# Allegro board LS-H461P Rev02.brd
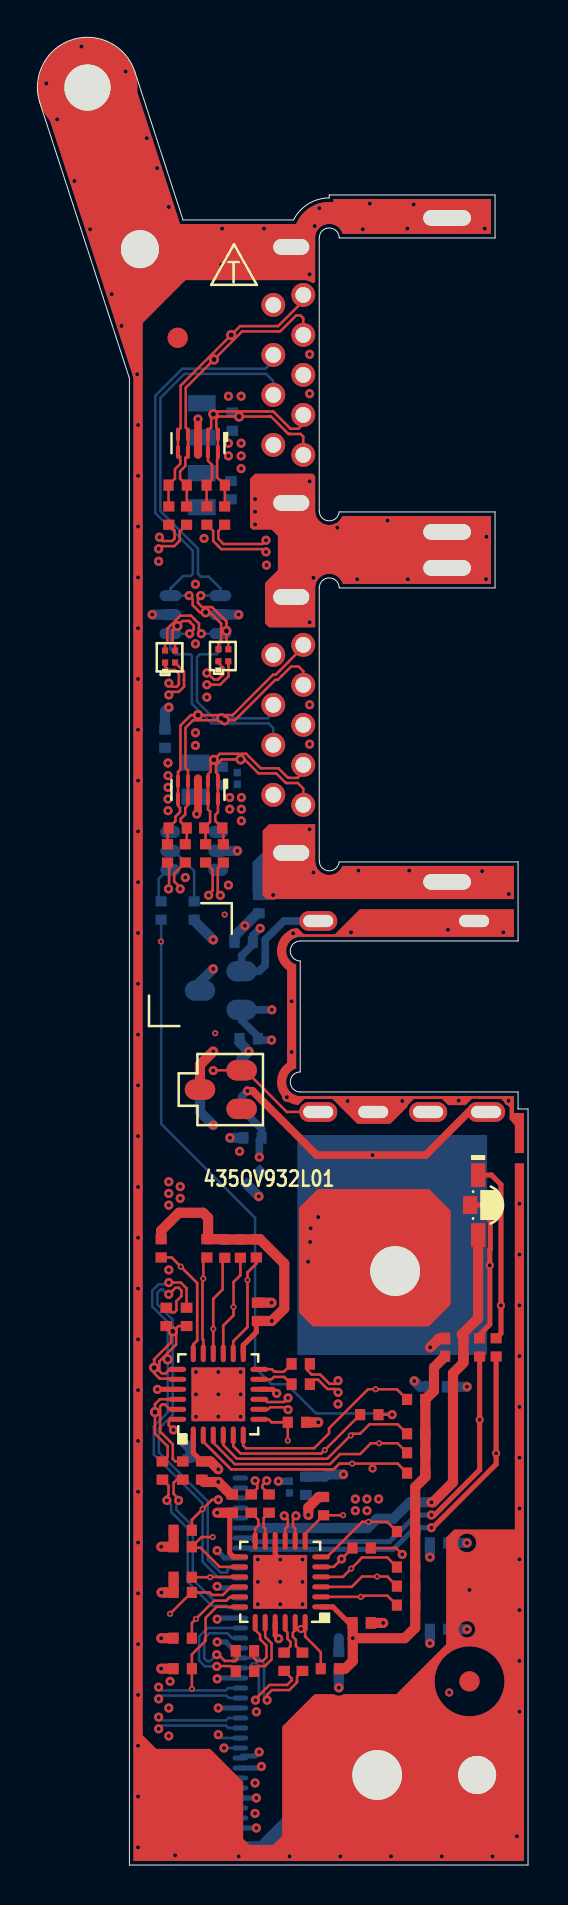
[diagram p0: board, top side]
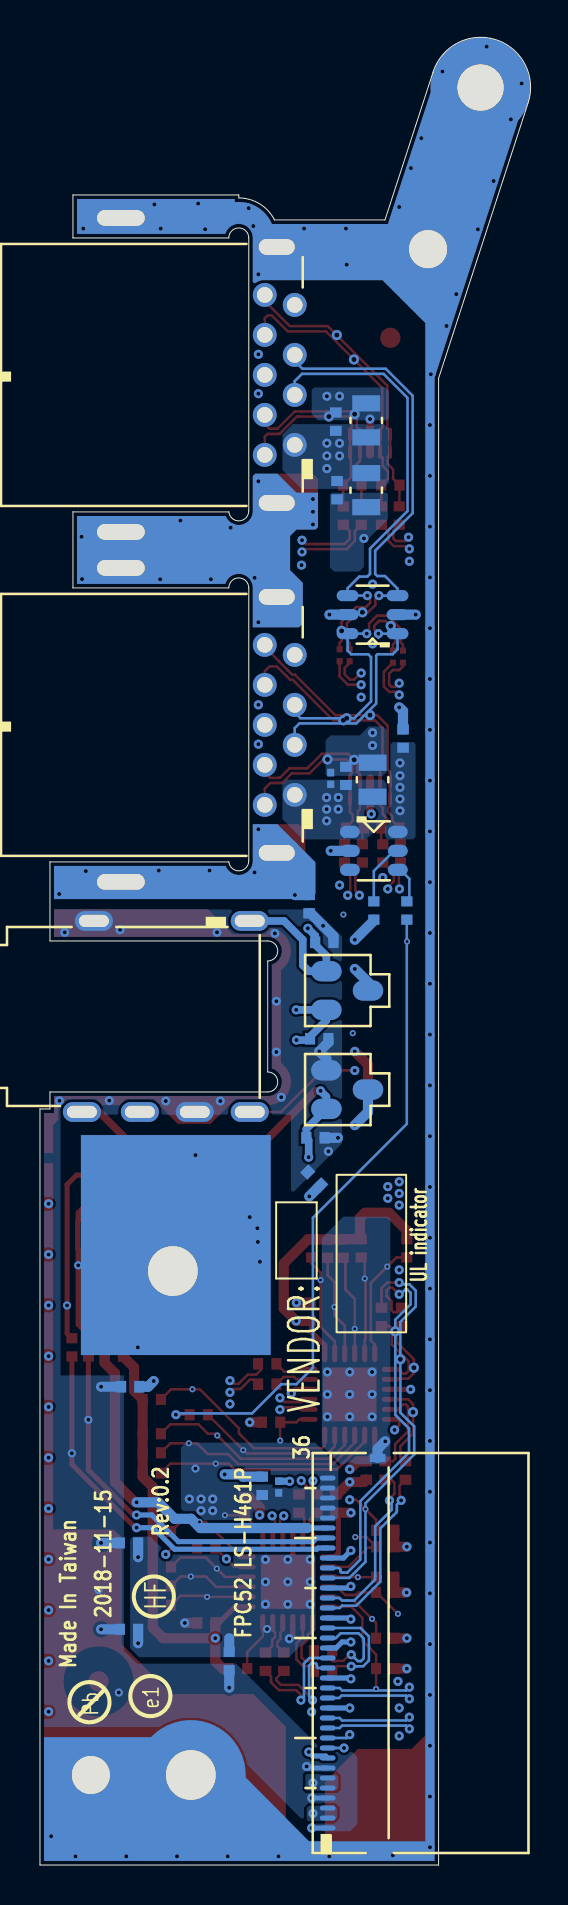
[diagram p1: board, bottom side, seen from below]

Outline 24.43 x 91.26 mm; copper layers: TOP, GND1, IN1, VCC, IN2, IN3, GND2, BOTTOM. Coordinates in mm from the lower left corner of the outline.
Outline path: 0,88.11 arc(1.6,91.26) 4.75,89.65 7.16,82.26 12.69,82.26 arc(13.43,83.06) 14.48,83.36 14.48,83.51 22.78,83.51 22.78,81.36 14.98,81.36 arc(14.48,81.86) 13.98,81.36 13.98,67.71 arc(14.45,67.21) 14.97,67.66 22.78,67.66 22.78,63.86 14.98,63.86 arc(14.48,64.36) 13.98,63.86 13.98,50.21 arc(14.45,49.71) 14.97,50.16 23.93,50.16 23.93,46.21 13.03,46.21 arc(12.53,45.71) 13.03,45.21 13.03,39.66 arc(12.53,39.16) 13.03,38.66 23.93,38.66 23.93,37.81 24.43,37.81 24.43,0 4.48,0 4.48,74.34 0,88.11

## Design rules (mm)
net group USB3: nets USB3_PRX_DTX_N2 USB3_PRX_DTX_N3 USB3_PRX_DTX_P2 USB3_PRX_DTX_P3 USB3_PTX_DRX_N2 USB3_PTX_DRX_N3 USB3_PTX_DRX_P2 USB3_PTX_DRX_P3 USB3_RX2_N_C USB3_RX2_P_C USB3_RX3_N_C USB3_RX3_P_C USB3_TX2_N_C USB3_TX2_P_C USB3_TX3_N_C USB3_TX3_P_C USB3RXDN2_C USB3RXDN3_C USB3RXDP2_C USB3RXDP3_C USB3RXN2_R USB3RXN3_R USB3RXP2_R USB3RXP3_R USB3TXDN2_C_R USB3TXDN3_C_R USB3TXDP2_C_R USB3TXDP3_C_R USB3TXN2_C USB3TXN2_RC USB3TXN3_C USB3TXN3_RC USB3TXP2_C USB3TXP2_RC USB3TXP3_C USB3TXP3_RC
net group USB 2.0: nets USB20_N2_C USB20_N3_C USB20_P2_C USB20_P3_C
nets with their own width: min track width 0.254; nets HDDHALT_LED# N98291261 N98291264 SATA_LED#
nets with their own width: min track width 0.381; nets HP_OUT_L HP_OUT_R INT_MIC
nets with their own width: min track width 0.508; nets +3VS +3VS_8713 +5VALW +USB_VCCA GND GNDA

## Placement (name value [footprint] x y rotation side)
CA33  100P_0402_50V8J  [C_0402]  11.1 36.36 180 bottom
CA48  10P_0402_50V8J  [C_0402]  10.65 46.14 180 bottom
CA49  10P_0402_50V8J  [C_0402]  10.91 41.31 180 bottom
CA50  10P_0402_50V8J  [C_0402]  10.96 47.59 90 bottom
CA51  10P_0402_50V8J  [C_0402]  11.03 34.65 225 bottom
CA52  10P_0402_50V8J  [C_0402]  20.37 23.92 180 bottom
CB1  0.01U_0402_16V7K  [C_0402]  10.89 27.2 90 top
CB2  0.1U_0402_16V7K  [C_0402]  8.1 20.18 270 top
CB3  .1U_0402_16V7K  [C_0402]  7.34 27.86 270 top
CB4  0.1U_0402_10V7K  [C_0402]  12.59 25.06 0 top
CB5  .1U_0402_16V7K  [C_0402]  6.32 27.86 270 top
CB6  0.1U_0402_10V7K  [C_0402]  12.59 24.04 0 top
CB7  .1U_0402_16V7K  [C_0402]  6.13 19.27 90 top
CB8  .1U_0402_16V7K  [C_0402]  7.15 19.27 90 top
CB9  0.01U_0402_16V7K  [C_0402]  15.64 12.1 0 top
CB10  0.1U_0402_16V7K  [C_0402]  9.62 17.62 90 top
CB11  .1U_0402_16V7K  [C_0402]  9.8 10.71 0 top
CB12  0.1U_0402_10V7K  [C_0402]  10.58 17.62 90 top
CB13  .1U_0402_16V7K  [C_0402]  9.8 9.69 0 top
CB14  0.1U_0402_10V7K  [C_0402]  11.46 17.62 90 top
CB15  .1U_0402_16V7K  [C_0402]  12.22 9.71 90 top
CB16  .1U_0402_16V7K  [C_0402]  13.14 9.71 90 top
CB17  10P_0402_50V8J  [C_0402]  21.19 26.33 180 top
CB18  10P_0402_50V8J  [C_0402]  13.31 18.5 90 bottom
CB19  10P_0402_50V8J  [C_0402]  9.62 71.72 90 bottom
CB20  10P_0402_50V8J  [C_0402]  9.11 54 90 bottom
CS1  10U_0402_6.3V6M  [C_0402]  6.26 55.87 90 bottom
CS3  0.1U_0201_10V6K  [C_0201]  12.48 18.61 90 bottom
CS4  1000P_0402_50V7K  [C_0402]  9.56 69.2 270 bottom
CS5  0.1U_0201_10V6K  [C_0201]  9.88 54.04 90 bottom
CS6  47U_0805_6.3V6M  [C_0805]  8.1 71.39 90 bottom
CS7  47U_0805_6.3V6M  [C_0805]  8.1 69.6 270 bottom
CS8  47U_0805_6.3V6M  [C_0805]  7.78 53.42 90 bottom
DA3  -  [L03ESDL5V0CC3-2_SOT23-3]  8.01 38.77 90 bottom
DA4  -  [L03ESDL5V0CC3-2_SOT23-3]  8.01 43.73 90 bottom
DA5  -  [L03ESDL5V0CC3-2_SOT23-3]  8.01 38.77 270 top
DM2  DT1140-04LP-7 U-DFN2510-10  [YSCLAMP0524P_SLP2510P8-10-9]  8.91 54.2 180 top
DM4  DT1140-04LP-7 U-DFN2510-10  [YSCLAMP0524P_SLP2510P8-10-9]  8.91 71.53 180 top
DM5  AZC099-04S.R7G_SOT23-6  [AZC099-04SPR7G_SOT23-6]  6.53 61.57 90 bottom
FM1  FM  [FIDUCIAL_C40M80]  6.89 76.37 0 top
FM2  FM  [FIDUCIAL_C40M80]  21.5 9.18 0 top
H1  HOLEA  [H_2P3]  2.38 88.88 0 top
H2  HOLEA  [H_1P9]  21.88 4.5 0 top
H3  HOLEA  [H_2P5]  16.88 4.5 0 top
H4  HOLEA  [H_2P5]  17.78 29.7 0 top
H5  HOLEA  [H_1P9]  5.01 80.8 0 top
JHP1  SINGA_2SJ3095-204111F  [SINGA_2SJ3095-204111F_6P-T]  13.93 47.21 90 bottom
JIO2  JXT_FP243A-036G1BM  [JXT_FP243A-036G1BM_36P]  10.03 1.85 90 bottom
JUSB2  ACON_TCRAR-9U1391  [ACON_TCRAR-9U1391_9P-T]  11.68 53.51 270 bottom
JUSB3  ACON_TCRAR-9U1391  [ACON_TCRAR-9U1391_9P-T]  11.68 71.01 270 bottom
LED3  B2102UYBS05P-000133_BYW  [LED_B2102UYBS05P-000133_3P]  21.53 33 90 top
LM1  DLM0NSN900HY2D_4P  [MURAT_DLM0NSN900HY2D_4P]  6.26 60.13 90 top
LM2  DLM0NSN900HY2D_4P  [MURAT_DLM0NSN900HY2D_4P]  8.93 60.19 90 top
NOREF  -  []  7.53 45.02 0 top
NOREF#2  -  []  8.57 79.01 0 top
NOREF#3  -  []  -4.41 -46.32 0 top
NOREF#4  -  []  5.01 80.8 0 top
NOREF#5  -  []  2.38 88.88 0 top
NOREF#6  -  []  16.88 4.5 0 top
NOREF#7  -  []  -75.73 44.96 0 top
NOREF#8  -  []  13.88 132.5 0 top
NOREF#9  -  []  21.88 4.5 0 top
NOREF#10  -  []  6.1 42.64 270 bottom
NOREF#11  -  []  29.5 23.61 180 bottom
NOREF#12  -  []  17.76 27.7 270 bottom
NOREF#13  -  []  12.64 33.29 270 bottom
PR1  0_0402_5%  [R0402_0OHM]  8.29 50.13 90 top
PR3  0_0402_5%  [R0402_0OHM]  9.18 50.13 90 top
PR4  0_0402_5%  [R0402_0OHM]  6.38 50.13 90 top
PR5  0_0402_5%  [R0402_0OHM]  7.27 50.13 90 top
PR6  0_0402_5%  [R0402_0OHM]  8.35 67.02 90 top
PR7  0_0402_5%  [R0402_0OHM]  9.24 67.02 90 top
PR8  0_0402_5%  [R0402_0OHM]  6.45 67.02 90 top
PR9  0_0402_5%  [R0402_0OHM]  7.34 67.02 90 top
R3  220_0402_5%  [R_0402]  22.01 26.34 270 top
R4  130_0402_5%  [R_0402]  22.83 26.34 270 top
RB1  0_0402_5%  [R_0402]  16.02 22.52 0 top
RB2  4.7K_0402_5%  [R_0402]  10.83 30.38 90 top
RB4  4.7K_0402_5%  [R_0402]  8.35 31.29 270 top
RB5  4.7K_0402_5%  [R_0402]  10.03 31.28 270 top
RB6  4.7K_0402_5%  [R_0402]  9.25 31.28 270 top
RB7  4.7K_0402_5%  [R_0402]  6.07 31.29 270 top
RB8  4.7K_0402_5%  [R_0402]  19.29 19.6 180 top
RB9  4.7K_0402_5%  [R_0402]  19.29 21.57 180 top
RB10  4.7K_0402_5%  [R_0402]  19.29 20.61 180 top
RB11  4.7K_0402_5%  [R_0402]  6.69 16.74 0 top
RB12  4.7K_0402_5%  [R_0402]  19.29 23.28 180 top
RB13  4.99K_0402_1%  [R_0402]  12.4 22.14 0 top
RB23  0_0402_5%  [R_0402]  15.64 15.85 0 top
RB24  4.7K_0402_5%  [R_0402]  7.6 15.91 180 top
RB25  4.7K_0402_5%  [R_0402]  6.69 11.34 0 top
RB26  4.7K_0402_5%  [R_0402]  6.69 14.39 0 top
RB27  4.7K_0402_5%  [R_0402]  6.69 13.63 0 top
RB28  4.7K_0402_5%  [R_0402]  6.69 9.82 0 top
RB29  4.7K_0402_5%  [R_0402]  18.78 12.99 180 top
RB30  4.7K_0402_5%  [R_0402]  18.78 14.9 180 top
RB31  4.7K_0402_5%  [R_0402]  18.78 13.95 180 top
RB32  4.7K_0402_5%  [R_0402]  18.78 16.68 180 top
RB34  4.7K_0402_5%  [R_0402]  14.97 9.82 180 top
RB35  4.99K_0402_1%  [R_0402]  14.19 17.49 90 top
RB46  0_0402_5%  [R0402_0OHM]  20.28 25.44 0 top
RG1  150_0402_5%  [R_0402]  9.13 51.86 180 top
RG2  150_0402_5%  [R_0402]  7.35 51.86 180 top
RG3  150_0402_5%  [R_0402]  9.25 69 180 top
RG4  150_0402_5%  [R_0402]  7.35 69 180 top
RH1  0_0402_5%  [R0402_0OHM]  6.07 47.27 90 bottom
RP1  0_0402_5%  [R_0402]  14.96 10.66 270 bottom
RP2  0_0402_5%  [R_0402]  19.52 11.79 0 bottom
RP3  0_0402_5%  [R_0402]  19.52 16.1 0 bottom
RS1  2.7K_0402_1%  [R_0402]  7.72 47.27 90 bottom
UB1  -  [PS8713BTQFN24GTR2_TQFN24_4X4]  7.67 21.48 0 top
UB2  -  [PS8713BTQFN24GTR2_TQFN24_4X4]  14.07 12.91 90 top
US1  SY6288F1ABC SOT23 6P  [SY6288F2ABC_SOT23-6]  8.92 51.66 270 bottom

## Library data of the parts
CA33 CA48-CA52 CB1-CB20 CS1 CS4 = C_0402
CS3 CS5 = C_0201
CS6-CS8 = C_0805
DA3-DA5 = L03ESDL5V0CC3-2_SOT23-3
DM2 DM4 = YSCLAMP0524P_SLP2510P8-10-9
DM5 = AZC099-04SPR7G_SOT23-6
FM1 FM2 = FIDUCIAL_C40M80
H1 = H_2P3
H2 H5 = H_1P9
H3 H4 = H_2P5
JHP1 = SINGA_2SJ3095-204111F_6P-T
JIO2 = JXT_FP243A-036G1BM_36P
JUSB2 JUSB3 = ACON_TCRAR-9U1391_9P-T
LED3 = LED_B2102UYBS05P-000133_3P
LM1 LM2 = MURAT_DLM0NSN900HY2D_4P
PR1 PR3-PR9 RB46 RH1 = R0402_0OHM
R3 R4 RB1 RB2 RB4-RB13 RB23-RB32 RB34 RB35 RG1-RG4 RP1-RP3 RS1 = R_0402
UB1 UB2 = PS8713BTQFN24GTR2_TQFN24_4X4
US1 = SY6288F2ABC_SOT23-6

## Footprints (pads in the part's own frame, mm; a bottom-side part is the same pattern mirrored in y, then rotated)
ACON_TCRAR-9U1391_9P-T
  round 1.194 hole 0.787: 1(0,0) 2(-2.5,0) 3(-4.5,0) 4(-7,0) 5(-7.5,-1.5) 6(-5.5,-1.5) 7(-3.5,-1.5) 8(-1.5,-1.5) 9(0.5,-1.5)
  oval 1.397x2.997 hole 0.787x2.388: 10(4.35,-8.7) 11(-11.35,-8.7)
  oval 1.397x2.388 hole 0.787x1.803: 12(-9.9,-0.9) 13(2.9,-0.9)
AZC099-04SPR7G_SOT23-6
  oval 0.559x1.092 smd: 1(0,0) 2(0.95,0) 3(1.9,0) 4(1.9,2.5) 5(0.95,2.5) 6(0,2.5)
C_0201
  rect 0.381x0.356 smd: 1(0,0) 2(0.584,0)
C_0402
  rect 0.508x0.584 smd: 1(0,0) 2(0.914,0)
C_0805
  rect 0.813x1.397 smd: 1(0,0) 2(1.702,0)
FIDUCIAL_C40M80
  round 1.016 smd: 1(0,0)
H_1P9
  round 2.413 hole 1.905: 1(0,0)
H_2P3
  round 2.819 hole 2.311: 1(0,0)
H_2P5
  round 2.997 hole 2.489: 1(0,0)
JXT_FP243A-036G1BM_36P
  oval 0.254x0.787 smd: 1(0,0) 2(0.5,0) 3(1,0) 4(1.5,0) 5(2,0) 6(2.5,0) 7(3,0) 8(3.5,0) 9(4,0) 10(4.5,0) 11(5,0) 12(5.5,0) 13(6,0) 14(6.5,0) 15(7,0) 16(7.5,0) 17(8,0) 18(8.5,0) 19(9,0) 20(9.5,0) 21(10,0) 22(10.5,0) 23(11,0) 24(11.5,0) 25(12,0) 26(12.5,0) 27(13,0) 28(13.5,0) 29(14,0) 30(14.5,0) 31(15,0) 32(15.5,0) 33(16,0) 34(16.5,0) 35(17,0) 36(17.5,0)
  rect 0.406x0.787 smd: 37(-1,-2.5) 38(18.5,-2.5)
L03ESDL5V0CC3-2_SOT23-3
  oval 1.016x1.524 smd: 1(0,0) 2(0.965,2.083) 3(-0.965,2.083)
LED_B2102UYBS05P-000133_3P
  rect 0.889x0.711 smd: 1(0,0)
  rect 1.194x0.711 smd: 2(-1.5,-0.4) 3(1.5,-0.4)
MURAT_DLM0NSN900HY2D_4P
  rect 0.305x0.305 smd: 1(0,0) 2(0.6,0) 3(0.6,-0.5) 4(0,-0.5)
PS8713BTQFN24GTR2_TQFN24_4X4
  oval 0.254x0.889 smd: 1(0,0) 2(0.5,0) 3(1,0) 4(1.5,0) 5(2,0) 6(2.5,0) 13(2.5,4.1) 14(2,4.1) 15(1.5,4.1) 16(1,4.1) 17(0.5,4.1) 18(0,4.1)
  oval 0.889x0.254 smd: 7(3.3,0.8) 8(3.3,1.3) 9(3.3,1.8) 10(3.3,2.3) 11(3.3,2.8) 12(3.3,3.3) 19(-0.8,3.3) 20(-0.8,2.8) 21(-0.8,2.3) 22(-0.8,1.8) 23(-0.8,1.3) 24(-0.8,0.8)
  rect 2.692x2.692 smd: 25(1.25,2.05)
R0402_0OHM
  rect 0.508x0.559 smd: 1(0,0) 2(0.914,0)
R_0402
  rect 0.508x0.559 smd: 1(0,0) 2(0.914,0)
SINGA_2SJ3095-204111F_6P-T
  oval 0.991x1.905 hole 0.61x1.499: 1(0,0) 2(-9.55,5.5) 3(0,7.8) 4(-9.55,8.4) 5(-9.55,0) 6(-9.55,2.75)
SY6288F2ABC_SOT23-6
  oval 0.61x0.991 smd: 1(0,0) 2(0.95,0) 3(1.9,0) 4(1.9,2.4) 5(0.95,2.4) 6(0,2.4)
YSCLAMP0524P_SLP2510P8-10-9
  oval 0.203x0.686 smd: 1(0,0) 2(0.5,0) 4(1.5,0) 5(2,0) 6(2,0.875) 7(1.5,0.875) 8(0.5,0.875) 9(0,0.875)
  oval 0.406x1.549 smd: 3(1,0.438)

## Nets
+3VS: CB17.1 JIO2.31 LED3.2 RB46.2
+3VS_8713: CB1.1 CB2.1 CB9.1 CB10.1 RB2.2 RB4.1 RB5.1 RB6.1 RB7.1 RB8.1 RB9.1 RB10.1 RB11.1 RB12.1 RB24.2 RB25.1 RB26.1 RB27.1 RB28.1 RB29.1 RB30.1 RB31.1 RB32.1 RB34.1 RB46.1 UB1.1 UB1.13 UB2.1 UB2.13
+5VALW: CB18.1 CS1.1 CS3.1 JIO2.32 JIO2.33 JIO2.34 JIO2.35 JIO2.36 US1.6
GND: CA50.2 CA51.2 CA52.2 CB1.2 CB2.2 CB9.2 CB10.2 CB17.2 CB18.2 CB19.2 CB20.2 CS1.2 CS3.2 CS4.2 CS5.2 CS6.2 CS7.2 CS8.2 DA3.1 DA4.1 DA5.1 DM2.3 DM4.3 DM5.2 H1.1(TP-1) H2.1(TP-1) H3.1(TP-1) H4.1(TP-1) H5.1(TP-1) JIO2.13 JIO2.16 JIO2.19 JIO2.22 JIO2.25 JIO2.28 JIO2.37 JIO2.38 JUSB2.4 JUSB2.7 JUSB2.10 JUSB2.11 JUSB2.12 JUSB2.13 JUSB3.4 JUSB3.7 JUSB3.10 JUSB3.11 JUSB3.12 JUSB3.13 RB13.2 RB35.2 RP1.1 RP2.1 RP3.1 RS1.1 UB1.10 UB1.21 UB1.25 UB2.10 UB2.21 UB2.25 US1.2
GNDA: CA33.2 CA48.2 CA49.2 CA50.1 CA51.1 CA52.1 DA3.2 JHP1.3 JHP1.6 JIO2.1 JIO2.4 JIO2.7 RP1.2 RP2.2 RP3.2
+USB_VCCA: CB19.1 CB20.1 CS4.1 CS5.1 CS6.1 CS7.1 CS8.1 DM5.5 JUSB2.1 JUSB3.1 US1.1
A1_DE0: RB27.2 UB2.16
A1_DE1: RB28.2 UB2.18
A1_EQ0: RB25.2 UB2.17
A1_EQ1: RB26.2 UB2.15
A_DE0: RB6.2 UB1.16
A_DE1: RB7.2 UB1.18
A_EQ0: RB4.2 UB1.17
A_EQ1: RB5.2 UB1.15
B1_DE0: RB31.2 UB2.3
B1_DE1: RB32.2 UB2.6
B1_EQ0: RB29.2 UB2.2
B1_EQ1: RB30.2 UB2.4
B_DE0: RB10.2 UB1.3
B_DE1: RB12.2 UB1.6
B_EQ0: RB8.2 UB1.2
B_EQ1: RB9.2 UB1.4
HDDHALT_LED#: JIO2.30 R3.2
HP_OUT_L: CA48.1 DA4.2 JHP1.1 JIO2.5 JIO2.6
HP_OUT_R: CA49.1 DA4.3 JHP1.2 JIO2.2 JIO2.3
I2C_EN3: RB11.2 UB1.24
I2C_EN4: RB34.2 UB2.24
INT_MIC: CA33.1 DA3.3 JHP1.4 JIO2.8
PLUG_IN#: DA5.3 JHP1.5 JIO2.9
SATA_LED#: JIO2.29 R4.2
TEST3: RB13.1 UB1.7
TEST4: RB35.1 UB2.7
USB3_PRX_DTX_N2: CB8.1 JIO2.24
USB3_PRX_DTX_N3: CB16.1 JIO2.18
USB3_PRX_DTX_P2: CB7.1 JIO2.23
USB3_PRX_DTX_P3: CB15.1 JIO2.17
USB3_PTX_DRX_N2: CB5.1 JIO2.27
USB3_PTX_DRX_N3: CB13.1 JIO2.21
USB3_PTX_DRX_P2: CB3.1 JIO2.26
USB3_PTX_DRX_P3: CB11.1 JIO2.20
USB3_RX2_N_C: CB8.2 UB1.23
USB3_RX2_P_C: CB7.2 UB1.22
USB3_RX3_N_C: CB16.2 UB2.23
USB3_RX3_P_C: CB15.2 UB2.22
USB3_TX2_N_C: CB5.2 UB1.20
USB3_TX2_P_C: CB3.2 UB1.19
USB3_TX3_N_C: CB13.2 UB2.20
USB3_TX3_P_C: CB11.2 UB2.19
USB3RXDN2_C: DM2.5 DM2.6 JUSB2.5 PR4.2 RG2.2
USB3RXDN3_C: DM4.5 DM4.6 JUSB3.5 PR8.2 RG4.2
USB3RXDP2_C: DM2.4 DM2.7 JUSB2.6 PR5.2 RG2.1
USB3RXDP3_C: DM4.4 DM4.7 JUSB3.6 PR9.2 RG4.1
USB3RXN2_R: PR4.1 UB1.8
USB3RXN3_R: PR8.1 UB2.8
USB3RXP2_R: PR5.1 UB1.9
USB3RXP3_R: PR9.1 UB2.9
USB3TXDN2_C_R: DM2.2 DM2.8 JUSB2.8 PR1.2 RG1.2
USB3TXDN3_C_R: DM4.2 DM4.8 JUSB3.8 PR6.2 RG3.2
USB3TXDP2_C_R: DM2.1 DM2.9 JUSB2.9 PR3.2 RG1.1
USB3TXDP3_C_R: DM4.1 DM4.9 JUSB3.9 PR7.2 RG3.1
USB3TXN2_C: CB6.1 UB1.11
USB3TXN2_RC: CB6.2 PR1.1
USB3TXN3_C: CB14.1 UB2.11
USB3TXN3_RC: CB14.2 PR6.1
USB3TXP2_C: CB4.1 UB1.12
USB3TXP2_RC: CB4.2 PR3.1
USB3TXP3_C: CB12.1 UB2.12
USB3TXP3_RC: CB12.2 PR7.1
USB20_N2: JIO2.14 LM1.4
USB20_N2_C: DM5.1 JUSB2.2 LM1.3
USB20_N3: JIO2.11 LM2.4
USB20_N3_C: DM5.4 JUSB3.2 LM2.3
USB20_P2: JIO2.15 LM1.1
USB20_P2_C: DM5.6 JUSB2.3 LM1.2
USB20_P3: JIO2.12 LM2.1
USB20_P3_C: DM5.3 JUSB3.3 LM2.2
USB_ISET_R: RS1.2 US1.5
USB_ON#: JIO2.10 RB1.2 RB23.2 RH1.1
USB_ON#_R: RH1.2 US1.4
N98220838: RB2.1 UB1.14
N98220917: RB1.1 UB1.5
N98223226: RB24.1 UB2.14
N98291261: LED3.1 R3.1
N98291264: LED3.3 R4.1
N98322636: RB23.1 UB2.5

Pads without a net: DA5 2; FM1 1; FM2 1; US1 3

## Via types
v1: diameter 0.457, hole 0.203, TOP to BOTTOM, 275 vias
v2: diameter 0.305, hole 0.152, TOP to BOTTOM, 25 vias
v3: diameter 0.508, hole 0.254, TOP to BOTTOM, 16 vias
v4: diameter 0.406, hole 0.203, TOP to BOTTOM, 10 vias

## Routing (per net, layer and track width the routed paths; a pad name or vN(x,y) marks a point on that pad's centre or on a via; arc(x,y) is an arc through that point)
+3VS: length 24.5
  TOP w0.508: LED3.2 21.93,27.34 21.12,26.52 CB17.1 RB46.2 21.19,25.11 20.67,24.59 20.67,19.14 19.67,18.14 v1(19.59,18.14)
  BOTTOM w0.254: 11.04,16.85 JIO2.31
  BOTTOM w0.508: v1(19.59,18.14) 18.51,18.14 17.69,17.31 16.86,17.31 16.4,16.85 11.04,16.85
+3VS_8713: length 50.1
  TOP w0.254: CB9.1 15.46,12.1 14.66,12.91 UB2.1 ; CB1.1 10.83,27.14 10.83,26.65 10.17,25.99 UB1.13 ; UB1.1 7.67,20.61 CB2.1 ; CB10.1 9.5,17.49 9.5,15.6 9.68,15.41 UB2.13
  TOP w0.508: CB9.1 15.66,12.1 v1(15.66,11.34) ; v1(6.07,15.91) RB24.2 RB11.1 ; RB7.1 6.07,31.73 6.96,32.61 8.16,32.61 8.42,32.36 8.42,31.36 RB4.1 9.23,31.29 RB6.1 10.03,31.28 RB5.1 10.82,31.28 RB2.2 11.01,31.29 12.23,30.07 12.23,27.83 v1(11.6,27.2) CB1.1 ; RB26.1 RB27.1 6.26,13.63 6.26,13.63 v1(6.08,13.63) ; v1(15.66,11.34) 18.26,11.34 18.78,11.86 RB29.1 RB31.1 RB30.1 RB32.1 18.78,18.9 19.29,19.41 RB8.1 RB10.1 RB9.1 RB12.1 19.72,23.71 19.72,24.88 RB46.1 ; v1(15.66,11.34) 15.66,10.2 15.27,9.82 RB34.1 ; CB2.1 8.53,20.18 v1(8.92,19.79) ; RB28.1 v1(6.07,9.82) ; RB25.1 v1(6.07,11.34) ; CB10.1 v1(8.87,17.62)
  IN1 w0.508: v1(6.07,15.91) 7.17,15.91 v1(8.87,17.62)
+5VALW:
  vias: v1(6.41,55.11) v1(6.41,54.47) v1(6.41,53.89) v1(6.41,53.3) v1(6.41,52.72) v1(6.45,34.16) v1(6.45,33.58) v1(6.45,33) v1(7.02,33.92) v1(7.02,33.34) v1(15.78,18.3) v1(15.78,17.72) v1(16.37,18.3) v1(16.37,17.72) v1(16.95,18.3) v4(16.65,19.83)
GND: length 38.5
  TOP w0.254: UB2.21 11.77,11.49 v1(11.95,11.32) ; UB1.21 v1(5.88,23.78) ; UB1.10 11.65,23.78 v1(11.85,23.58) ; UB2.10 11.77,15.53 v1(12.02,15.28)
  TOP w0.381: DM2.3 7.91,52.68 7.84,52.62 v1(7.84,52.55) ; DM4.3 v1(7.91,72.3)
  TOP w0.508: CB9.2 v1(17.18,12.1) ; RB13.2 v1(13.93,22.14) ; RB35.2 13.95,18.4 13.43,17.88 v1(13.43,17.5) ; DA5.1 8.01,40.02 v1(8.67,40.68) ; CB1.2 v1(11.59,28.12) ; CB2.2 8.21,19.15 v1(8.92,19.15) 9.55,18.53 CB10.2 ; v1(19.53,25.88) 19.97,26.33 CB17.2
  BOTTOM w0.254: JIO2.16 9.03,9.35 8.99,9.31 v1(8.87,9.31) ; v1(8.87,15.72) 8.87,15.72 9.23,15.35 JIO2.28 ; v1(8.87,11.15) 9.31,11.15 9.61,10.85 JIO2.19 ; v1(8.87,12.29) 8.92,12.35 JIO2.22 ; JIO2.13 v1(8.92,7.85) ; JIO2.25 8.95,13.85 v1(8.87,13.93)
  BOTTOM w0.356: CS3.2 11.93,19.19 v1(11.93,19.19)
  BOTTOM w0.381: JIO2.37 7.13,0.85 v1(6.77,0.48)
  BOTTOM w0.508: RP2.1 v1(19.52,11.09) ; v1(8.67,46.27) 7.72,47.22 RS1.1 ; DM5.2 v1(5.62,62.52) ; JIO2.38 7.53,20.8 v1(7.15,21.18) ; DA5.1 8.01,37.66 v1(8.67,37) ; CA51.2 v1(10.95,33.43) ; v1(6.45,57.89) 6.26,57.7 CS1.2 ; CB18.2 14.27,19.42 14.39,19.53 v1(15.19,19.53) ; v1(18.74,24.2) 19.02,23.92 CA52.2 ; v1(8.67,44.81) 8.01,44.15 DA4.1 ; CA50.2 v1(11.67,48.5) ; RP3.1 v1(19.52,15.39) ; RP1.1 14.96,11.34 ; US1.2 v1(9.88,50.71)
  vias: v1(0.32,89.09) v1(0.86,87.29) v1(1.72,84.21) v1(2.07,90.93) v1(2.51,81.79) v1(3.59,78.55) v1(4.08,76.96) v1(4.28,89.68) v1(4.87,74.54) v1(4.91,72) v1(4.91,69.46) v1(4.91,66.92) v1(4.91,64.38) v1(4.91,61.84) v1(4.91,59.3) v1(4.91,56.76) v1(4.91,54.22) v1(4.91,51.68) v1(4.91,49.14) v1(4.91,46.6) v1(4.91,44.06) v1(4.91,41.52) v1(4.91,38.98) v1(4.91,36.44) v1(4.91,33.9) v1(4.91,31.36) v1(4.91,28.82) v1(4.91,26.28) v1(4.91,23.74) v1(4.91,21.2) v1(4.91,18.66) v1(4.91,16.12) v1(4.91,13.58) v1(4.91,11.04) v1(4.91,8.5) v1(4.91,5.96) v1(4.91,3.42) v1(4.91,0.88) v1(5.34,86.35) v1(5.86,84.85) v1(5.94,65.19) v1(6.45,82.91) v1(6.45,29.76) v1(6.51,9.18) v1(6.45,7.85) v1(6.45,6.45) v1(7.27,49.38) v1(7.78,64.05) v1(7.78,61.06) v1(7.78,56.62) v1(7.78,55.98) v1(7.81,24.65) v1(7.81,23.53) v1(7.81,22.42) v1(8.21,66.33) v1(8.35,58.4) v1(8.92,24.65) v1(8.92,23.53) v1(8.92,22.42) v1(9.11,81.83) v1(9.43,73.45) v1(9.43,49) v1(9.95,0.43) v1(10.07,73.45) v1(10.04,24.65) v1(10.04,23.53) v1(10.04,22.42) v1(10.77,68.3) v1(10.77,67.67) v1(10.77,67.03) v1(10.91,15.28) v1(10.91,14.16) v1(10.91,13.04) v1(10.83,7.66) v1(11.21,81.83) v1(11.34,65) v1(12.02,14.16) v1(12.02,13.04) v1(12.49,0.43) v1(13.14,15.28) v1(13.14,14.16) v1(13.14,13.04) v1(13.42,30.16) v1(13.5,79.54) v1(13.5,75.54) v1(13.5,73.57) v1(13.5,69.19) v1(13.5,62.14) v1(13.5,58.01) v1(13.5,56.05) v1(13.5,51.79) v1(13.52,31.15) v1(13.55,31.84) v1(13.69,64.36) v1(13.69,49.63) v1(13.75,81.95) v1(13.98,82.85) v1(13.93,32.4) v1(14.88,66.87) v1(14.92,23.05) v1(15.03,0.43) v1(15.87,64.29) v1(15.94,49.73) v1(16.16,81.79) v1(16.51,83.08) v1(17.4,67.23) v1(17.57,0.43) v1(18.39,81.83) v1(18.41,64.29) v1(18.48,49.73) v1(18.7,83.03) v1(20.11,0.43) v1(22.13,49.7) v1(22.26,81.83) v1(22.32,64.3) v1(22.35,66.42) v1(22.65,0.43) v1(23.47,48.55) v1(23.87,1.44) v1(24,33.07) v1(24,30.53) v1(24,27.99) v1(24,25.45) v1(24,22.91) v1(24,20.37) v1(24,17.83) v1(24,15.29) v1(24,12.75) v1(24,10.21) v1(24,7.67) v4(9.08,80.02) v4(13.06,11.8) v4(21.5,13.76)
GNDA: length 11
  BOTTOM w0.254: v1(11.08,4.93) 11,4.85 JIO2.7 ; JIO2.4 v1(10.83,3.35) ; JIO2.1 v1(10.83,1.85)
  BOTTOM w0.508: CA49.2 9.99,41.14 v1(10.45,40.68) 10.09,40.32 DA3.2 ; RP3.2 v1(21.37,16.1) ; CA50.1 10.88,47.59 v1(10.26,46.97) 9.74,46.44 CA48.2 ; RP1.2 v1(14.96,8.87) ; CA33.2 v1(9.51,36.36) ; CA52.1 v1(21.37,23.92) ; RP2.2 v1(21.37,11.79)
  vias: v1(9.99,35.69) v1(12.35,38.39) v1(12.6,43.19) v1(12.6,40.65) v1(12.67,46.58) v1(15.4,38.2) v1(15.57,46.64) v1(18.13,38.2) v1(20.42,46.76) v1(20.96,38.22) v1(23.19,46.64) v1(23.45,38.22) v4(20.48,8.62)
+USB_VCCA: length 0.9
  BOTTOM w0.508: DM5.5 v1(9.94,62.52)
  vias: v1(9.43,71.1) v1(9.43,70.46) v1(9.5,53.38) v1(9.5,52.79) v1(10.07,71.1) v1(10.07,70.46) v1(10.07,69.83) v1(10.08,53.38) v1(10.08,52.79) v1(10.08,52.21)
A1_DE0: length 4.1
  TOP w0.127: v2(6.51,12.56) 7.58,13.63 RB27.2 8.49,13.63 8.62,13.5 9.15,13.5 9.56,13.91 UB2.16
A1_DE1: length 5.8
  TOP w0.127: v2(7.6,8.8) RB28.2 7.6,10.53 8.29,11.22 8.29,12.36 8.84,12.91 UB2.18
A1_EQ0: length 3.7
  TOP w0.127: UB2.17 9.52,13.41 9.32,13.22 8.71,13.22 v2(7.81,12.31) 7.6,12.1 RB25.2
A1_EQ1: length 2.4
  TOP w0.127: UB2.15 8.54,14.41 v2(8.52,14.39) RB26.2
A_DE0: length 5
  TOP w0.135: UB1.16 v2(8.67,26.81) 8.67,28.31 9.14,28.78 9.14,30.26 RB6.2
A_DE1: length 5.9
  TOP w0.135: RB7.2 6.59,30.38 v2(7.04,29.92) 7.87,29.1 7.87,26.23 7.67,26.03 UB1.18
A_EQ0: length 4.9
  TOP w0.127: RB4.2 8.17,30.2 v2(8.17,29.33)
  TOP w0.135: v2(8.17,29.33) 8.13,29.28 8.13,26.29 8.17,26.25 UB1.17
A_EQ1: length 5.1
  TOP w0.127: 9.69,29.15 v2(9.69,27.9)
  TOP w0.135: UB1.15 9.17,26.97 9.69,27.48 v2(9.69,27.9) ; 9.69,29.15 10.03,29.49 RB5.2
B1_DE0: length 4.2
  TOP w0.127: RB31.2 17.39,14.42 v2(16.87,14.42) 16.12,14.42 15.6,13.91 UB2.3
B1_DE1: length 4.7
  TOP w0.127: RB32.2 17.38,17.16 v2(16.44,17.16) 16.13,17.16 14.37,15.41 UB2.6
B1_EQ0: length 4
  TOP w0.127: UB2.2 v2(16.06,13.41) 16.18,13.41 16.24,13.47 17.39,13.47 RB29.2
B1_EQ1: length 4.4
  TOP w0.127: RB30.2 17.39,15.38 16.12,15.38 15.99,15.25 15.99,15.23 v2(15.58,14.82) 15.17,14.41 UB2.4
B_DE0: length 11.1
  TOP w0.127: RB10.2 17.9,21.09 v2(16.98,21.09) 16.56,21.09 16.02,20.55 15.02,20.55 14.52,20.04 9.75,20.04 8.67,21.12 UB1.3
B_DE1: length 10.3
  TOP w0.127: UB1.6 10.17,20.97 10.31,20.84 13.72,20.84 14.47,21.58 14.47,21.84 16.42,23.79 v2(16.8,23.79) 17.87,23.79 RB12.2
B_EQ0: length 11.4
  TOP w0.127: RB8.2 17.9,20.07 v2(15.63,20.07)
  TOP w0.135: UB1.2 8.17,21.17 9.56,19.78 14.7,19.78 14.99,20.07 v2(15.63,20.07)
B_EQ1: length 10.9
  TOP w0.127: RB9.2 17.9,22.04 16.5,22.04 16.02,21.57 15.64,21.57 v2(15.55,21.48) 15.54,21.48 14.38,20.31 9.86,20.31 9.17,21 UB1.4
HDDHALT_LED#: length 19.2
  TOP w0.254: v1(19.59,17.5) 19.75,17.5 22.01,19.76 v4(22.01,22.26) R3.2
  BOTTOM w0.254: v1(19.59,17.5) 18.83,17.5 17.5,16.17 10.77,16.17 10.58,16.35 JIO2.30
HP_OUT_L: length 68.9
  IN3 w0.381: v1(10.77,4.1) 11.04,4.1 15.28,8.35 20.6,8.35 21.94,9.69 21.94,33.76 20,35.7 12.22,35.7 9.75,38.17 9.75,45.57 v1(11.02,46.84)
  BOTTOM w0.381: v1(11.02,46.84) 10.65,46.47 CA48.1 10.65,46.03 10.09,45.47 DA4.2 10.97,44.69 11.27,45 11.27,46.27 12.21,47.21 JHP1.1
HP_OUT_R: length 74.9
  IN1 w0.381: v1(11.6,42.76) 11.02,42.18 11.02,38.52 12.8,36.74 18.51,36.74 19.43,37.66 JHP1.2
  IN3 w0.381: v1(10.77,2.58) 11.13,2.58 15.76,7.21 21.07,7.21 23.08,9.22 23.08,34.23 20.47,36.84 12.7,36.84 11.02,38.52 11.02,40.68 v1(11.59,41.25)
  BOTTOM w0.381: v1(11.6,42.76) DA4.3 10.09,42.24 10.91,41.43 CA49.1 10.97,41.25 v1(11.59,41.25)
I2C_EN3: length 7.7
  TOP w0.127: v1(8.92,18.26) 8.61,18.26 v2(8.14,17.79)
  TOP w0.135: UB1.24 6.54,22.28 6.45,22.19 6.45,21.99 v1(6.68,21.76) ; RB11.2 7.6,17.26 v2(8.14,17.79)
  IN1 w0.127: v1(8.92,18.26) 6.7,20.49 6.7,21.73 v1(6.68,21.76)
I2C_EN4: length 2.6
  TOP w0.127: UB2.24 13.27,11.43 14.06,10.64 RB34.2
INT_MIC: length 64.5
  TOP w0.381: v1(10.38,38.71) 10.64,38.71 13.85,35.5 v4(16.65,35.5) 19.3,35.5 21.46,37.66 JHP1.4
  IN3 w0.381: v1(10.98,35.39) 10.98,35.33 11.75,34.56 19.53,34.56 20.77,33.31 20.77,10.39 19.88,9.49 14.81,9.49 v1(10.97,5.65)
  BOTTOM w0.254: JIO2.8 10.13,5.45 10.77,5.45 v1(10.97,5.65)
  BOTTOM w0.381: v1(10.38,38.71) 10.09,38.42 DA3.3 11.1,36.81 CA33.1 10.98,36.24 v1(10.98,35.39)
PLUG_IN#: length 50.8
  TOP w0.127: JHP1.5 12.35,37.66 10.27,39.74 DA5.3 8.68,39.74 v1(8.67,39.73)
  IN3 w0.127: v1(8.67,39.73) 8.67,37.81 10.45,36.03 10.45,31.34 18.64,23.15 18.64,12.04 17.15,10.55 14.42,10.55 9.72,5.85 v1(9.21,5.85)
  BOTTOM w0.135: JIO2.9 v1(9.21,5.85)
  vias: v2(8.77,41.59)
SATA_LED#: length 20
  TOP w0.254: v1(19.59,16.87) 19.66,16.87 22.83,20.04 v4(22.83,20.59) R4.2
  BOTTOM w0.254: JIO2.29 10.51,15.85 10.58,15.79 17.69,15.79 18.77,16.87 v1(19.59,16.87)
TEST3: length 2.4
  TOP w0.127: RB13.1 v2(12.4,21.22)
  TOP w0.135: RB13.1 11.59,22.14 11.44,22.28 UB1.7
TEST4: length 2.6
  TOP w0.127: v2(15.17,17.49) RB35.1 13.27,16.57 UB2.7
USB3_PRX_DTX_N2: length 8.7
  TOP w0.127: CB8.1 6.84,19.27 6.69,19.11 6.69,18.56 6.94,18.31 v1(6.94,18.23)
  BOTTOM w0.127: JIO2.24 9.43,13.35 9.3,13.23 9.04,13.23 9.04,13.22 8.7,13.22 7.65,14.27 7.65,14.43 7.65,14.44 7.65,16.94 6.83,17.76 6.83,18.12 v1(6.94,18.23)
USB3_PRX_DTX_N3: length 5.9
  TOP w0.127: v1(11.37,8.24) 11.37,8.51 11.61,8.75 12.48,8.75 12.87,9.14 12.87,9.19 12.86,9.43 13.14,9.7 CB16.1
  BOTTOM w0.127: JIO2.18 10.53,10.35 10.53,10.35 10.64,10.35 10.75,10.35 10.75,10.35 10.94,10.35 11.21,10.08 11.21,8.4 v1(11.37,8.24)
USB3_PRX_DTX_P2: length 8.9
  TOP w0.127: v1(6.35,18.23) 6.35,18.42 6.43,18.5 6.43,18.96 CB7.1
  BOTTOM w0.127: v1(6.35,18.23) 6.56,18.02 6.56,17.73 6.57,17.72 6.57,17.65 6.72,17.49 6.73,17.49 7.39,16.83 7.39,14.44 7.39,14.44 7.39,14.33 7.4,14.33 7.4,14.17 8.59,12.97 9.3,12.97 9.31,12.96 9.31,12.96 9.43,12.85 JIO2.23
USB3_PRX_DTX_P3: length 5.8
  TOP w0.127: CB15.1 12.61,9.32 12.61,9.24 12.37,9.01 11.49,9.01 10.78,8.3 v1(10.78,8.24)
  BOTTOM w0.127: JIO2.17 10.52,9.85 10.57,9.9 10.57,10.02 10.64,10.09 10.84,10.09 10.96,9.97 10.96,8.42 v1(10.78,8.24)
USB3_PTX_DRX_N2: length 20.3
  TOP w0.127: CB5.1 6.55,27.64 6.73,27.64 6.83,27.74 6.83,28.2 7.08,28.45 7.08,28.73 6.94,28.87 6.79,28.87 6.62,28.7 6.61,28.7 v1(6.45,28.54)
  BOTTOM w0.127: v1(6.45,28.54) 6.38,28.54 6.14,28.78 6.04,28.78 5.88,28.61 5.88,28.04 6.65,27.27 v3(6.65,26.68) 6.65,22.73 6.65,22.52 6.17,22.04 6.17,22.04 5.96,21.83 5.96,20.63 8.39,18.19 8.39,16.63 8.4,16.62 8.4,15.27 9.05,14.62 9.33,14.62 9.38,14.67 9.38,14.77 9.46,14.85 JIO2.27
USB3_PTX_DRX_N3: length 5.5
  TOP w0.127: v1(8.85,9.93) 8.87,9.93 8.88,9.95 9.54,9.95 CB13.1
  BOTTOM w0.127: JIO2.21 8.37,11.85 8.37,11.84 7.96,11.43 7.96,10.23 8.25,9.94 8.54,9.94 8.55,9.93 v1(8.85,9.93)
USB3_PTX_DRX_P2: length 20.4
  TOP w0.127: CB3.1 7.34,28.84 7.05,29.12 6.7,29.12 6.7,29.12 v1(6.45,29.12)
  BOTTOM w0.127: JIO2.26 10.02,14.36 8.94,14.36 8.14,15.16 8.14,18.09 5.7,20.53 5.7,21.93 6.06,22.3 6.07,22.3 6.39,22.62 6.39,22.73 v3(6.39,25.29) 6.39,27.16 5.62,27.93 5.62,28.72 5.94,29.04 6.16,29.04 6.17,29.05 6.37,29.05 v1(6.45,29.12)
USB3_PTX_DRX_P3: length 5.5
  TOP w0.127: v1(8.85,10.52) 8.94,10.52 9.25,10.2 9.65,10.2 9.66,10.19 9.67,10.2 9.79,10.2 9.86,10.28 9.86,10.64 CB11.1
  BOTTOM w0.13: JIO2.20 9.61,11.35 9.38,11.59 8.48,11.59 8.22,11.33 8.22,10.33 8.36,10.2 8.52,10.2 8.67,10.35 8.7,10.35 8.85,10.5 v1(8.85,10.52)
USB3_RX2_N_C: length 4.4
  TOP w0.127: UB1.23 6.5,22.78 6.26,23.03 6.11,23.03 6.01,22.93 6.01,22.37 6.01,22.37 6.01,21.81 6.01,21.8 6.01,21.68 6.49,21.19 6.65,21.04 6.65,20.33 6.64,20.32 6.77,20.18 CB8.2
USB3_RX2_P_C: length 4.5
  TOP w0.127: CB7.2 6.38,20.43 6.38,20.43 6.39,20.44 6.39,20.93 6.39,20.94 5.76,21.57 5.76,21.7 5.76,21.7 5.76,22.48 5.76,22.48 v3(5.76,22.65) 5.76,22.82 5.75,22.82 5.75,23.03 5.81,23.09 5.81,23.09 6,23.29 6.37,23.29 6.37,23.28 UB1.22
USB3_RX3_N_C: length 1.7
  TOP w0.127: UB2.23 12.77,11.74 12.66,11.62 12.66,11.41 12.81,11.26 12.81,10.95 CB16.2
USB3_RX3_P_C: length 1.7
  TOP w0.127: CB15.2 12.54,10.94 12.54,11.15 12.39,11.3 12.39,11.62 12.27,11.74 UB2.22
USB3_TX2_N_C: length 4.1
  TOP w0.127: UB1.20 6.52,24.28 6.48,24.33 6.4,24.33 6.39,24.32 6,24.32 5.97,24.35 5.96,24.35 5.71,24.6 v3(5.71,24.87) 5.71,25.22 5.71,25.28 5.71,25.29 6.56,26.13 6.56,26.71 CB5.2
USB3_TX2_P_C: length 4.1
  TOP w0.127: CB3.2 6.93,26.95 6.82,26.84 6.82,26.82 6.82,26.82 6.82,26.6 6.82,26.6 6.82,26.03 5.98,25.19 5.98,24.71 6.11,24.58 6.28,24.58 6.49,24.78 UB1.19
USB3_TX3_N_C: length 3.1
  TOP w0.127: CB13.2 10.97,9.95 11.26,9.95 11.59,10.28 11.59,11.08 11.27,11.4 UB2.20
USB3_TX3_P_C: length 3.1
  TOP w0.127: UB2.19 10.77,11.75 11.02,11.51 11.02,11.29 11.34,10.97 11.34,10.38 11.16,10.2 11.01,10.2 10.85,10.2 10.71,10.34 CB11.2
USB3RXDN2_C: length 14.2
  TOP w0.127: JUSB2.5 13.18,60.91 12.46,60.2 12.46,60.18 12,59.72 12,59.72 11.8,59.52 11.67,59.52 9.65,57.5 v3(7.91,57.5) 7.55,57.5 7.03,56.97 7.03,54.97 7.02,54.97 7.02,54.77 6.91,54.66 DM2.5 DM2.6 6.91,52.97 7.01,52.87 7.01,52.65 6.78,52.42 6.78,52.2 RG2.2 6.38,51.8 PR4.2
USB3RXDN3_C: length 14.6
  TOP w0.127: JUSB3.5 13.18,78.21 11.92,76.95 10.02,76.95 v3(9.57,76.5) 7.04,73.97 7.04,71.86 6.91,71.73 DM4.5 DM4.6 6.91,70.52 7.02,70.42 7.02,70.23 7.02,70.23 7.02,70.06 6.76,69.8 6.76,69.32 RG4.2 6.44,67.95 PR8.2
USB3RXDP2_C: length 14.1
  TOP w0.127: JUSB2.6 13.18,59.69 12.94,59.93 12.58,59.93 12.11,59.47 11.91,59.26 11.78,59.26 9.91,57.4 9.91,57.4 9.75,57.24 v3(9.24,57.24) 7.66,57.24 7.28,56.87 7.28,54.86 7.41,54.74 DM2.4 DM2.7 7.41,53.01 7.27,52.87 7.27,52.54 7.04,52.31 7.04,52.16 RG2.1 7.35,51.12 PR5.2
USB3RXDP3_C: length 14.6
  TOP w0.127: PR9.2 7.35,67.95 RG4.1 7.34,69 7.01,69.33 7.01,69.69 7.28,69.96 7.28,70.33 7.27,70.34 7.27,70.36 7.41,70.5 DM4.7 DM4.4 7.41,71.77 7.3,71.88 7.3,73.87 v3(8.71,75.28) 10.12,76.69 11.91,76.69 11.92,76.69 12.03,76.69 12.82,77.48 13.04,77.48 13.18,77.35 JUSB3.6
USB3RXN2_R: length 32.2
  TOP w0.127: v1(12.42,22.77) 12.3,22.89 11.52,22.89 11.41,22.78 UB1.8 ; PR4.1 6.46,50.05 6.46,48.83 v1(6.44,48.81)
  IN1 w0.135: v1(6.44,48.81) 6.55,48.69 6.55,48.17 6.17,47.79 6.17,35.4 8.39,33.18 8.39,29.56 9.03,28.92 9.03,28.57 9.03,28.56 9.03,28.29 11.15,26.17 11.15,23.3 11.15,23.29 11.56,22.88 12.14,22.88 12.16,22.9 12.29,22.9 v1(12.42,22.77)
USB3RXN3_R: length 56.1
  TOP w0.127: UB2.8 12.77,16.82 12.67,16.92 12.67,17.32 v1(12.81,17.46) ; PR8.1 6.74,66.73 6.74,66.33 6.62,66.21 6.13,66.21 5.95,66.39 5.95,66.4 5.98,66.36 5.98,66.4 v1(5.98,66.4)
  IN1 w0.135: v1(12.81,17.46) 12.7,17.57 12.7,18 13.14,18.44 13.14,28.22 9.65,31.71 9.65,33.58 9.62,33.61 9.62,33.64 7.36,35.91 7.36,47.21 7.34,47.23 7.34,47.35 7.97,47.98 7.97,49.08 7.98,49.09 7.98,49.67 7.97,49.67 7.97,51.01 7.34,51.64 7.34,60.09 6.7,60.72 6.7,65.89 6.39,66.2 6.14,66.2 5.95,66.39 5.95,66.4 5.98,66.36 5.98,66.4 v1(5.98,66.4)
USB3RXP2_R: length 32.1
  TOP w0.127: v1(12.42,23.36) 12.21,23.15 11.36,23.15 11.23,23.28 UB1.9 ; v1(7.02,48.81) 7.02,48.88 6.72,49.19 6.72,49.57 PR5.1
  IN1 w0.135: v1(12.42,23.36) 12.24,23.18 12.04,23.18 12.03,23.16 11.68,23.16 11.43,23.41 11.43,23.42 11.43,26.28 9.31,28.4 9.31,28.45 9.31,28.45 9.31,29.03 9.31,29.04 8.67,29.67 8.67,33.29 6.45,35.51 6.45,47.68 6.83,48.06 6.83,48.62 v1(7.02,48.81)
USB3RXP3_R: length 55.9
  TOP w0.127: PR9.1 6.99,66.68 6.99,66.22 6.72,65.95 6.08,65.95 v1(5.94,65.81) ; UB2.9 12.27,16.82 12.4,16.95 12.4,17.28 v1(12.23,17.46)
  IN1 w0.135: v1(12.23,17.46) 12.42,17.65 12.42,18.12 12.86,18.56 12.86,28.11 9.37,31.6 9.37,33.47 9.34,33.49 9.34,33.53 7.08,35.79 7.08,47.09 7.06,47.12 7.06,47.46 7.69,48.1 7.69,49.2 7.7,49.2 7.7,49.55 7.69,49.56 7.69,50.89 7.06,51.53 7.06,59.97 6.42,60.61 6.42,65.77 6.28,65.92 6.05,65.92 v1(5.94,65.81)
USB3TXDN2_C_R: length 10.1
  TOP w0.127: JUSB2.8 13.18,54.63 12.9,54.36 12.46,54.36 12.45,54.37 12.41,54.37 11.93,54.84 11.04,54.84 10.32,55.56 9,55.56 v3(8.7,55.27) 8.54,55.11 8.54,54.67 8.41,54.54 DM2.2 DM2.8 8.41,52.79 8.52,52.68 8.52,52.16 RG1.2 8.29,51.78 PR1.2
USB3TXDN3_C_R: length 10.4
  TOP w0.127: JUSB3.8 13.18,72.06 12.94,71.82 12.54,71.82 11.67,72.69 11.67,72.69 8.83,72.69 8.83,72.68 8.81,72.68 v3(8.68,72.55) 8.57,72.44 8.57,71.89 8.41,71.73 DM4.2 DM4.8 8.41,70.21 8.61,70.01 8.61,69.27 8.61,69.27 RG3.2 8.34,67.95 PR6.2
USB3TXDP2_C_R: length 10.1
  TOP w0.127: JUSB2.9 13.18,53.83 12.9,54.11 12.35,54.11 12.35,54.11 12.3,54.11 11.83,54.58 10.94,54.58 10.24,55.28 10.04,55.28 v3(10.04,55.28) 9.69,55.28 9.69,55.28 9.09,55.28 8.81,55 8.81,54.64 8.91,54.54 DM2.1 DM2.9 8.91,52.64 8.77,52.51 8.77,52.21 RG1.1 9.18,51.8 PR3.2
USB3TXDP3_C_R: length 10.3
  TOP w0.127: JUSB3.9 13.18,71.43 13.05,71.56 13.05,71.56 12.51,71.56 12.51,71.56 12.43,71.56 12.28,71.71 12.28,71.72 11.57,72.43 11.46,72.43 11.46,72.43 v3(9.97,72.43) 8.93,72.43 8.93,72.43 8.92,72.43 8.83,72.33 8.83,71.87 8.91,71.78 DM4.1 DM4.9 8.91,70.32 8.87,70.28 8.87,69.39 RG3.1 9.25,67.95 PR7.2
USB3TXN2_C: length 1.8
  TOP w0.127: UB1.11 11.59,24.28 11.71,24.41 12.22,24.41 12.23,24.4 CB6.1
USB3TXN2_RC: length 32
  TOP w0.127: v1(14.92,23.64) 14.75,23.8 14.39,23.8 13.92,24.27 13.74,24.27 CB6.2 ; v1(8.44,48.49) 8.44,48.53 8.64,48.73 8.64,49.77 PR1.1
  IN1 w0.135: v1(14.92,23.64) 14.77,23.79 14.22,23.79 13.75,24.26 13.75,28.32 10.23,31.84 10.23,33.94 7.95,36.22 7.95,47.28 8.58,47.92 8.58,48.3 8.44,48.44 v1(8.44,48.49)
USB3TXN3_C: length 1.6
  TOP w0.127: CB14.1 11.2,17.35 11.2,16.9 11.27,16.82 UB2.11
USB3TXN3_RC: length 54.5
  TOP w0.127: PR6.1 8.67,66.7 8.67,66.21 8.92,65.95 8.92,65.95 9.07,65.8 11.17,65.8 v1(11.31,65.66) ; v1(11.35,19.22) 11.13,19 11.13,18.86 CB14.2
  IN3 w0.127: v1(11.31,65.66) 11.15,65.82 10.96,65.82 10.89,65.75 10.89,65.74 10.86,65.71 10.86,65.7 10.84,65.67 10.84,49.14 7.78,46.08 7.78,36.13 7.79,36.13 7.78,36.12 7.78,36.11 9.13,34.76 9.13,30.81 10.99,28.94 10.99,21.99 10.99,21.77 11.18,21.58 11.18,19.38 v1(11.35,19.22)
USB3TXP2_C: length 1.8
  TOP w0.127: UB1.12 11.61,24.78 11.73,24.67 11.82,24.67 11.82,24.66 12.2,24.66 CB4.1
USB3TXP2_RC: length 32
  TOP w0.127: CB4.2 13.37,24.92 13.37,24.75 13.6,24.52 14.03,24.52 14.49,24.06 14.76,24.06 v1(14.92,24.22) ; PR3.1 8.9,49.85 8.9,48.62 v1(9.03,48.49)
  IN1 w0.135: v1(9.03,48.49) 9.03,48.44 8.86,48.28 8.86,47.8 8.23,47.17 8.23,36.34 10.51,34.05 10.51,31.96 14.03,28.44 14.03,24.38 14.34,24.07 14.77,24.07 v1(14.92,24.22)
USB3TXP3_C: length 1.6
  TOP w0.127: UB2.12 10.77,16.82 10.93,16.98 10.93,17.26 CB12.1
USB3TXP3_RC: length 54.5
  TOP w0.127: PR7.1 8.93,66.7 8.93,66.31 9.18,66.06 11.12,66.06 v1(11.31,66.24) ; CB12.2 10.88,18.83 10.88,19.1 10.88,19.11 v1(10.77,19.22)
  IN3 w0.127: v1(11.31,66.24) 11.15,66.08 10.86,66.08 10.67,65.89 10.67,65.89 10.6,65.82 10.6,65.8 10.58,65.78 10.58,49.25 7.53,46.19 7.53,36.23 7.52,36.23 7.52,36.01 8.87,34.66 8.87,30.7 10.74,28.83 10.74,21.88 10.74,21.88 10.74,21.66 10.93,21.47 10.93,19.38 v1(10.77,19.22)
USB20_N2: length 59.5
  TOP w0.127: LM1.4 6.85,60.04 6.85,60.04 7.21,59.67 7.21,59.24 7.21,58.92 6.95,58.66 6.6,58.66 v1(6.45,58.51)
  IN3 w0.127: v1(5.94,8.31) 6.1,8.47 6.11,8.47 6.15,8.5 6.93,8.5 7.64,9.21 7.64,18.87 7.64,19.12 6.21,20.55 6.21,23.08 6.22,23.1 6.22,23.16 6.58,23.51 6.58,23.84 6.58,23.84 6.58,24.4 5.93,25.05 5.93,58.43 6.13,58.64 6.32,58.64 v1(6.45,58.51)
  BOTTOM w0.127: v1(5.94,8.31) 6.1,8.47 9.33,8.47 9.45,8.35 JIO2.14
USB20_N2_C: length 13.9
  TOP w0.127: v1(7.49,61.57) 7.7,61.78 7.7,61.85 7.7,61.97 7.54,62.13 7.54,62.13 7.46,62.21 7.46,62.21 7.13,62.21 6.88,61.95 ; LM1.3 6.76,61.03 6.64,61.15 6.64,61.71 6.88,61.95 ; v3(6.88,61.96) 6.88,61.95
  BOTTOM w0.127: JUSB2.2 11.68,56.85 11.44,57.08 9.18,57.08 8.59,57.08 7.6,58.07 7.6,60.47 7.53,60.54 6.78,60.54 6.53,60.79 DM5.1 6.53,61.57 v1(7.49,61.57) 7.49,61.36
USB20_N3: length 62.6
  TOP w0.127: v1(8.35,59.02) 8.61,59.02 8.61,59.01 8.71,59.01 8.71,59.02 9.01,59.02 9.43,59.43 9.43,59.44 9.43,59.45 9.43,59.96 9.43,59.97 LM2.4
  IN3 w0.127: v1(8.35,59.02) 8.04,59.02 7.89,58.88 7.89,57.96 8.57,57.28 8.57,49.32 6.92,47.67 6.92,35.67 8.21,34.38 8.21,34.2 8.21,34.2 8.21,31.32 7.33,30.44 7.33,22.26 8.42,21.17 8.42,21.05 8.42,21.05 8.42,20.94 8.42,8.87 8.43,8.86 8.43,8.64 8.42,8.63 8.42,8.61 8.34,8.54 6.8,6.99 6.13,6.99 v1(5.94,6.81)
  BOTTOM w0.127: v1(5.94,6.81) 6.1,6.97 9.31,6.97 9.43,6.85 JIO2.11
USB20_N3_C: length 23
  TOP w0.127: v1(8.05,63.48) 7.91,63.34 7.91,63.11 8.11,62.9 8.61,62.9 9.17,62.34 9.18,62.34 9.33,62.19 9.33,62.11 9.33,62.11 9.33,61.71 v3(9.33,61.71) 9.33,61.71 9.33,61.21 9.43,61.11 LM2.3
  BOTTOM w0.127: v1(8.05,63.48) 9.03,63.48 DM5.4 9.03,63.84 8.44,64.43 8.04,64.43 7.91,64.56 7.91,65.82 6.03,67.7 6.03,73.36 7.23,74.56 11.31,74.56 11.68,74.2 JUSB3.2
USB20_P2: length 59.4
  TOP w0.127: LM1.1 6.26,59.93 6.44,59.75 6.77,59.75 6.95,59.57 6.95,59.13 6.95,59.03 6.84,58.92 6.62,58.92 v1(6.45,59.09)
  IN3 w0.127: v1(6.45,59.09) 6.25,58.89 6.03,58.89 5.67,58.54 5.67,24.94 6.32,24.3 6.32,23.73 6.32,23.62 5.97,23.27 5.97,23.2 5.95,23.19 5.95,20.44 7.38,19.01 7.38,18.98 7.38,9.32 6.82,8.76 6.07,8.76 v1(5.94,8.89)
  BOTTOM w0.127: JIO2.15 9.43,8.85 9.31,8.73 6.1,8.73 v1(5.94,8.89)
USB20_P2_C: length 13.7
  TOP w0.127: v1(8.07,61.57) 7.96,61.69 7.96,61.84 7.96,62.07 7.72,62.31 7.72,62.31 7.56,62.47 7.49,62.47 7.49,62.47 7.46,62.47 7.02,62.47 6.37,61.82 6.37,61.14 6.26,61.03 LM1.2
  BOTTOM w0.127: JUSB2.3 11.68,57.63 11.39,57.34 v3(9.08,57.34) 8.7,57.34 7.86,58.18 7.86,60.4 8,60.54 8.85,60.54 9.03,60.73 DM5.6 8.08,61.57 v1(8.07,61.57)
USB20_P3: length 62.5
  TOP w0.127: v1(8.35,59.6) 8.39,59.6 8.71,59.27 8.91,59.27 9.17,59.54 9.17,59.55 9.18,59.56 9.18,59.86 8.93,60.11 LM2.1
  IN3 w0.127: v1(5.94,7.39) 6.08,7.25 6.69,7.25 8.16,8.72 8.16,8.74 8.17,8.75 8.17,8.76 8.16,8.76 8.16,21.04 8.16,21.06 7.07,22.16 7.07,30.54 7.95,31.42 7.95,34.28 6.67,35.56 6.67,47.78 8.32,49.43 8.32,57.17 7.64,57.85 7.64,58.88 7.64,58.88 7.64,58.98 7.77,59.12 7.77,59.13 8.24,59.6 v1(8.35,59.6)
  BOTTOM w0.127: v1(5.94,7.39) 6.1,7.23 9.3,7.23 9.43,7.35 JIO2.12
USB20_P3_C: length 23
  TOP w0.127: LM2.2 8.93,61.11 9.07,61.25 9.07,62.08 8.51,62.64 v3(8.29,62.64) 8,62.64 7.64,63 7.64,63.3 v1(7.46,63.48)
  BOTTOM w0.127: v1(7.46,63.48) 7.46,63.47 DM5.3 6.53,63.82 7.16,64.45 7.55,64.45 7.65,64.56 7.65,65.72 5.77,67.6 5.77,73.47 7.12,74.82 11.29,74.82 11.68,75.21 JUSB3.3
USB_ISET_R: length 3.1
  BOTTOM w0.127: RS1.2 7.72,49.7 6.71,50.71 US1.5
  vias: v2(9.24,47.52)
USB_ON#: length 58.4
  TOP w0.127: RB23.2 17.81,15.85 v1(18.13,15.53)
  TOP w0.135: RB1.2 v1(17.62,22.52)
  IN3 w0.127: v1(18.13,15.53) 18.13,12.04 16.93,10.83 12.61,10.83 8.92,7.15 v1(8.92,6.52)
  IN3 w0.142: v1(17.62,22.52) 17.69,22.52 18.13,22.07 v1(18.13,15.53)
  BOTTOM w0.127: v1(17.62,22.52) 17.56,22.58 13.81,22.58 12.35,24.04 11.59,24.04 10.77,24.87 10.77,32.36 6.07,37.06 6.07,46.17 ; 6.07,46.17 RH1.1 ; 6.07,46.17 v2(6.05,46.18)
  BOTTOM w0.135: JIO2.10 9.09,6.35 v1(8.92,6.52)
USB_ON#_R: length 1.9
  BOTTOM w0.127: RH1.2 5.94,48.31 5.94,49.32 6.39,49.76 US1.4
N98220838: length 5.3
  TOP w0.135: RB2.1 10.83,30.07 10.38,29.63 v2(10.38,29.25) 10.38,26.9 9.67,26.19 UB1.14
N98220917: length 7.8
  TOP w0.127: UB1.5 9.67,20.94 10.04,20.58 14.08,20.58 v2(14.25,20.75) RB1.1
N98223226: length 4
  TOP w0.127: UB2.14 8.99,14.91 8.04,15.86 7.65,15.86 RB24.1 8.09,16.4 v2(8.64,16.4)
N98291261: length 7.7
  TOP w0.254: LED3.1 22.13,33 22.51,32.62 22.51,32.23 22.54,32.2 22.54,30.8 22.51,30.77 v4(22.51,29.99) 22.51,29.99 22.51,27.03 22.01,26.52 R3.1
N98291264: length 9.1
  TOP w0.254: R4.1 23.07,26.58 v4(23.07,27.98) 23.07,34.02 22.6,34.5 LED3.3
N98322636: length 2
  TOP w0.127: UB2.5 14.7,14.91 v1(15.1,15.3) RB23.1

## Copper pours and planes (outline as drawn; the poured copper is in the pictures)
+3VS_8713 on IN2: 9.81,10.39 8.61,11.6 8.61,20.04 8.8,20.23 10.13,20.23 10.32,20.04 10.32,18.84 10.58,18.58 11.4,18.58 11.65,18.84 11.65,21.57 11.34,21.88 11.34,27.28 11.53,27.47 12.48,27.47 14.19,25.76 14.19,17.12 15.85,15.47 15.85,10.83 15.4,10.39
+3VS_8713 on IN2: 5.69,16.36 7.08,16.36 7.21,16.23 7.21,9.63 7.02,9.44 5.75,9.44 5.62,9.56 5.62,16.3
+5VALW on BOTTOM: 17.37,17.82 17.24,17.69 16.67,17.69 16.23,17.25 14.77,17.25 14.7,17.18 9.69,17.18 9.5,17.37 9.5,19.97 10.65,21.12 17.13,21.12 17.37,20.88
+5VALW on BOTTOM: 7.02,51.28 5.75,51.28 5.62,51.41 5.62,56.05 5.72,56.15 6.77,56.15 6.89,56.02 6.89,52.17 7.15,51.92 7.15,51.41
+5VALW on VCC: 5.62,32.42 5.62,55.41 8.57,55.41 8.8,55.18 8.8,32.66 8.57,32.42
+5VALW on IN2: 14.58,17.25 15.15,16.68 17.89,16.68 18.98,17.77 18.98,24.91 9.21,34.68 6.1,34.68 5.69,34.27 5.69,32.55 5.94,32.3 7.97,32.3 14.58,25.69
GND on TOP (solid shape): 20.56,32.7 20.56,28.03 19.47,26.94 13.65,26.94 12.96,27.62 12.96,32.86 13.9,33.8 19.47,33.8
GND on TOP (solid shape): 13.77,50.21 14.35,49.52 15.13,49.96 23.72,49.96 23.72,48.3 11.33,48.3 11.15,48.49 11.15,51.73 11.46,52.05 13.77,52.05
GND on TOP (solid shape): 13.77,69.44 13.77,67.71 14.35,67.02 15.13,67.46 22.57,67.46 22.57,64.06 15.15,64.06 15.14,64.1 14.53,64.56 13.86,64.19 13.85,64.17 13.79,64.02 13.77,63.86 13.77,61.89 11.46,61.89 11.27,62.08 11.27,64.11 11.91,64.75 11.91,66.46 11.59,66.78 10.64,66.78 10.51,66.9 10.51,69.32 10.77,69.57 13.65,69.57
GND on TOP (solid shape): outline of 348 points within 0.08,0.2 24.22,91.18
GND on BOTTOM (solid shape): 22.38,25.5 12.88,25.5 12.88,36.5 22.38,36.5
GND on BOTTOM (solid shape): 13.77,50.21 14.35,49.52 15.13,49.96 23.72,49.96 23.72,48.3 10.89,48.3 10.64,48.55 10.64,50.14 12.54,52.05 13.77,52.05
GND on BOTTOM (solid shape): 13.77,69.44 13.77,67.71 14.35,67.02 15.13,67.46 22.57,67.46 22.57,64.06 15.15,64.06 15.14,64.1 14.53,64.56 13.86,64.19 13.85,64.17 13.79,64.02 13.77,63.86 13.77,61.89 11.46,61.89 11.27,62.08 11.27,64.11 11.91,64.75 11.91,66.46 11.59,66.78 10.64,66.78 10.51,66.9 10.51,68.62 11.59,68.62 12.54,69.57 13.65,69.57
GND on BOTTOM (solid shape): 0.19,88.17 1.67,91.06 4.56,89.59 7.01,82.06 12.82,82.06 13.57,82.91 14.68,83.15 14.68,83.31 22.57,83.31 22.57,81.56 15.15,81.56 15.14,81.6 14.36,82.05 13.77,81.36 13.77,79.2 13.72,79.11 13.61,79.12 13.49,79.19 13.36,79.24 13.32,79.25 7.28,79.25 5.14,77.1 5.14,1.18 10.96,1.18 12.14,2.36 12.14,2.38 16.15,6.39 24.22,6.39 24.22,0.2 4.68,0.2 4.68,74.37
GND on IN1 (solid shape): 19.72,32.49 19.72,25.44 19.4,25.12 17.94,25.12 11.72,31.34 11.72,33 19.21,33
GND on IN1 (solid shape): 13.77,50.21 14.35,49.52 15.13,49.96 23.72,49.96 23.72,48.3 11.33,48.3 11.15,48.49 11.15,51.73 11.46,52.05 13.77,52.05
GND on IN1 (solid shape): 17.56,15.53 17.56,12.04 17.24,11.72 10.45,11.72 10.07,12.1 10.07,15.29 14.73,15.29 14.74,15.24 14.75,15.19 14.77,15.14 14.8,15.09 14.83,15.05 14.87,15.01 14.92,14.98 14.97,14.96 15.02,14.95 15.07,14.94 15.12,14.94 15.18,14.95 15.23,14.96 15.28,14.98 15.32,15.01 15.36,15.05 15.39,15.09 15.42,15.14 15.44,15.19 15.46,15.24 15.46,15.29 15.46,15.34 15.45,15.4 15.43,15.45 15.41,15.5 15.38,15.54 15.34,15.58 15.3,15.61 15.25,15.64 15.2,15.66 15.15,15.67 15.1,15.67 15.04,15.67 14.99,15.66 14.94,15.64 14.89,15.61 14.85,15.58 14.81,15.54 14.78,15.5 14.76,15.45 14.74,15.4 14.73,15.34 14.73,15.29 10.07,15.29 10.07,15.53 10.45,15.91 17.18,15.91
GND on IN1 (solid shape): 13.77,69.44 13.77,67.71 14.35,67.02 15.13,67.46 22.57,67.46 22.57,64.06 15.15,64.06 15.14,64.1 14.53,64.56 13.86,64.19 13.85,64.17 13.79,64.02 13.77,63.86 13.77,61.89 11.27,61.89 11.27,64.11 11.91,64.75 11.91,66.46 11.59,66.78 10.64,66.78 10.51,66.9 10.51,69.32 10.77,69.57 13.65,69.57
GND on IN1 (solid shape): 0.19,88.17 1.67,91.06 4.56,89.59 7.01,82.06 12.82,82.06 13.57,82.91 14.68,83.15 14.68,83.31 22.57,83.31 22.57,81.56 15.15,81.56 15.14,81.6 14.36,82.05 13.77,81.36 13.77,79.22 13.41,79.22 13.32,79.25 7.28,79.25 5.14,77.1 5.14,0.66 10.7,0.66 16.43,6.39 23.47,6.39 23.77,6.69 23.77,35.09 24.22,35.09 24.22,0.2 4.68,0.2 4.68,74.37
GND on IN2 (solid shape): 19.72,32.49 19.72,25.69 19.59,25.57 18.83,25.57 12.35,32.04 12.35,32.81 12.54,33 19.21,33
GND on IN2 (solid shape): 13.77,50.21 14.35,49.52 15.13,49.96 23.72,49.96 23.72,48.3 11.33,48.3 11.15,48.49 11.15,51.73 11.46,52.05 13.77,52.05
GND on IN2 (solid shape): 13.77,69.44 13.77,67.71 14.35,67.02 15.13,67.46 22.57,67.46 22.57,64.06 15.15,64.06 15.14,64.1 14.53,64.56 13.86,64.19 13.85,64.17 13.79,64.02 13.77,63.86 13.77,61.89 11.27,61.89 11.27,64.11 11.91,64.75 11.91,66.46 11.59,66.78 10.64,66.78 10.51,66.9 10.51,69.32 10.77,69.57 13.65,69.57
GND on IN2 (solid shape): 0.19,88.17 1.67,91.06 4.56,89.59 7.01,82.06 12.82,82.06 13.57,82.91 14.68,83.15 14.68,83.31 22.57,83.31 22.57,81.56 15.15,81.56 15.14,81.6 14.36,82.05 13.77,81.36 13.77,79.2 13.72,79.11 13.61,79.12 13.49,79.19 13.36,79.24 13.32,79.25 11.15,79.25 10.32,78.42 10.32,73.38 8.29,71.35 5.88,71.35 5.14,70.61 5.14,0.66 10.7,0.66 16.43,6.39 23.47,6.39 23.77,6.69 23.77,35.09 24.22,35.09 24.22,0.2 4.68,0.2 4.68,74.37
GND on IN3 (solid shape): 19.72,32.49 19.72,25.44 19.4,25.12 17.94,25.12 11.72,31.34 11.72,33 19.21,33
GND on IN3 (solid shape): 13.77,50.21 14.35,49.52 15.13,49.96 23.72,49.96 23.72,48.3 11.33,48.3 11.15,48.49 11.15,51.73 11.46,52.05 13.77,52.05
GND on IN3 (solid shape): 17.56,15.53 17.56,12.04 17.24,11.72 10.45,11.72 10.07,12.1 10.07,15.3 14.73,15.3 14.74,15.25 14.75,15.2 14.77,15.15 14.8,15.1 14.83,15.06 14.87,15.02 14.91,14.99 14.96,14.97 15.02,14.95 15.07,14.94 15.12,14.94 15.18,14.95 15.23,14.97 15.28,14.99 15.32,15.02 15.36,15.06 15.4,15.1 15.42,15.15 15.44,15.2 15.46,15.25 15.46,15.3 15.46,15.36 15.44,15.41 15.42,15.46 15.4,15.51 15.36,15.55 15.32,15.59 15.28,15.62 15.23,15.64 15.18,15.66 15.12,15.67 15.07,15.67 15.02,15.66 14.96,15.64 14.91,15.62 14.87,15.59 14.83,15.55 14.8,15.51 14.77,15.46 14.75,15.41 14.74,15.36 14.73,15.3 10.07,15.3 10.07,15.53 10.45,15.91 17.18,15.91
GND on IN3 (solid shape): 13.77,69.44 13.77,67.71 14.35,67.02 15.13,67.46 22.57,67.46 22.57,64.06 15.15,64.06 15.14,64.1 14.53,64.56 13.86,64.19 13.85,64.17 13.79,64.02 13.77,63.86 13.77,61.89 11.27,61.89 11.27,64.11 11.91,64.75 11.91,66.46 11.59,66.78 10.64,66.78 10.51,66.9 10.51,69.32 10.77,69.57 13.65,69.57
GND on IN3 (solid shape): 0.19,88.17 1.67,91.06 4.56,89.59 7.01,82.06 12.82,82.06 13.57,82.91 14.68,83.15 14.68,83.31 22.57,83.31 22.57,81.56 15.15,81.56 15.14,81.6 14.36,82.05 13.77,81.36 13.77,79.25 7.28,79.25 5.14,77.1 5.14,0.66 10.7,0.66 16.43,6.39 23.47,6.39 23.77,6.69 23.77,35.09 24.22,35.09 24.22,0.2 4.68,0.2 4.68,74.37
GND on BOTTOM: 7.02,32.42 9.24,32.42 10.32,31.34 10.32,20.23 10.13,20.04 7.15,20.04 6.89,20.3 6.89,32.3
GND on BOTTOM: 7.08,54.65 7.08,56.74 7.27,56.94 7.97,56.94 8.42,56.49 9.88,56.49 10.13,56.24 10.13,54.52 10.07,54.46 7.27,54.46
GND on BOTTOM: 7.08,72.24 10.51,72.24 10.83,72.56 10.83,73.76 10.7,73.89 7.15,73.89 6.96,73.7 6.96,72.37
GND on BOTTOM: 10.7,15.53 18,15.53 18.89,16.42 19.78,16.42 19.91,16.3 19.91,10.83 19.47,10.39 11.97,10.39 10.64,11.72 10.64,15.47
GND on BOTTOM: 7.08,68.62 9.81,68.62 9.91,68.52 9.91,64.89 9.71,64.68 8.44,64.68 8.21,64.91 8.21,66.09 7.02,67.29 7.02,68.56
GND on GND1, GND2: 4.68,0.2 4.68,74.37 0.19,88.17 1.67,91.06 4.56,89.59 7.01,82.06 12.82,82.06 13.57,82.91 14.68,83.14 14.68,83.31 22.57,83.31 22.57,81.56 15.15,81.56 14.37,82.06 13.77,81.36 13.77,67.71 14.35,67.02 15.13,67.46 22.57,67.46 22.57,64.06 15.15,64.06 14.37,64.56 13.77,63.86 13.77,50.21 14.35,49.52 15.13,49.96 23.72,49.96 23.72,48.3 10.47,48.3 8.8,46.63 8.8,35.87 11.61,33.06 19.23,33.06 19.72,32.57 19.72,10.94 19.36,10.58 14.41,10.58 10.22,6.39 8.82,6.39 8.04,5.61 8.04,1.84 8.69,1.18 10.93,1.18 16.14,6.39 24.22,6.39 24.22,0.2
GND on VCC: 4.68,0.2 4.68,74.37 0.19,88.17 1.67,91.06 4.56,89.59 7.01,82.06 12.82,82.06 13.57,82.91 14.68,83.14 14.68,83.31 22.57,83.31 22.57,81.56 15.15,81.56 14.37,82.06 13.77,81.36 13.77,67.71 14.35,67.02 15.13,67.46 22.57,67.46 22.57,64.06 15.15,64.06 14.37,64.56 13.77,63.86 13.77,50.21 14.35,49.52 15.13,49.96 23.72,49.96 23.72,48.3 9.31,48.3 9.31,55.39 8.78,55.92 5.11,55.92 5.11,31.92 8.78,31.92 9.31,32.45 9.31,35.09 9.58,35.09 11.61,33.06 19.23,33.06 19.72,32.57 19.72,10.94 19.36,10.58 14.41,10.58 10.22,6.39 8.82,6.39 8.04,5.61 8.04,1.84 8.69,1.18 10.93,1.18 16.14,6.39 24.22,6.39 24.22,0.2
GNDA on TOP (solid shape): 23.72,46.41 13.03,46.41 12.33,45.83 12.79,45.04 12.82,45.03 12.82,39.83 12.79,39.82 12.33,39.04 13.03,38.45 23.72,38.45 23.72,37.6 24.22,37.6 24.22,35.6 23.77,35.6 23.77,37 23.63,37.13 23.63,37.15 23.5,37.28 23.5,37.89 23.09,38.3 22.82,38.3 22.77,38.3 22.73,38.3 21.93,38.3 21.92,38.32 21.62,38.32 21.3,38 20.43,38 20.12,38.3 18.72,38.3 18.4,37.99 18.4,37.92 17.53,37.06 15.88,37.06 14.64,38.3 13.23,38.3 12.93,38 11.91,38.86 12.37,40.11 12.37,44.75 11.9,45.98 12.89,46.86 13.2,46.55 14.77,46.55 14.87,46.65 14.87,46.65 16.01,47.8 23.72,47.8
GNDA on IN3 (solid shape): 23.72,46.41 13.03,46.41 12.33,45.83 12.79,45.04 12.82,45.03 12.82,39.83 12.79,39.82 12.33,39.04 13.03,38.45 23.72,38.45 23.72,37.6 24.22,37.6 24.22,35.6 23.77,35.6 23.77,37.15 23.58,37.15 23.48,37.25 23.48,37.89 23.06,38.3 21.56,38.3 21.25,38 20.47,38 20.16,38.3 19.06,38.3 19.05,38.32 18.7,38.32 17.94,37.55 17.94,37.47 17.69,37.21 15.97,37.21 14.88,38.3 13.52,38.3 13.51,38.32 12.91,38.32 12.65,38.06 11.88,39 12.37,40.11 12.37,44.75 11.89,45.95 12.81,46.85 13.11,46.55 14.76,46.55 16.01,47.8 23.72,47.8
GNDA on BOTTOM, IN1, IN2: 8.9,1.69 8.54,2.05 8.54,5.4 9.03,5.88 10.42,5.88 14.61,10.07 19.57,10.07 20.23,10.73 20.23,32.78 19.44,33.57 11.82,33.57 9.31,36.08 9.31,46.42 10.68,47.79 23.72,47.79 23.72,46.41 13.03,46.41 12.33,45.81 12.82,45.03 12.82,39.83 12.33,39.05 13.03,38.45 23.72,38.45 23.72,37.6 24.22,37.6 24.22,6.9 15.93,6.9 10.73,1.69
GNDA on GND1, GND2: 8.9,1.69 8.54,2.05 8.54,5.39 9.03,5.88 10.43,5.88 14.62,10.07 19.57,10.07 20.23,10.73 20.23,32.78 19.44,33.57 11.82,33.57 9.31,36.09 9.31,46.42 10.68,47.79 23.72,47.79 23.72,46.41 13.03,46.41 12.33,45.81 12.82,45.03 12.82,39.83 12.33,39.05 13.03,38.45 23.72,38.45 23.72,37.6 24.22,37.6 24.22,6.9 15.93,6.9 10.72,1.69
GNDA on VCC: 8.9,1.69 8.54,2.05 8.54,5.39 9.03,5.88 10.43,5.88 14.62,10.07 19.57,10.07 20.23,10.73 20.23,32.78 19.44,33.57 11.82,33.57 9.31,36.09 9.31,46.42 10.68,47.79 23.72,47.79 23.72,46.41 13.03,46.41 12.33,45.81 12.82,45.03 12.82,39.83 12.33,39.05 13.03,38.45 23.72,38.45 23.72,37.6 24.22,37.6 24.22,6.9 15.93,6.9 10.72,1.69
+USB_VCCA on IN2 (solid shape): 10.38,71.22 10.38,51.73 10.32,51.66 9.24,51.66 8.73,52.17 8.73,71.1 9.05,71.41 10.19,71.41
+USB_VCCA on BOTTOM: 7.21,72.05 11.78,72.05 12.29,71.54 12.29,69.76 11.34,68.81 7.27,68.81 6.96,69.13 6.96,71.79
+USB_VCCA on BOTTOM: 8.1,51.28 7.08,52.3 7.08,54.08 7.27,54.27 12.1,54.27 12.29,54.08 12.29,52.3 11.27,51.28
+USB_VCCA on IN1: 10.19,71.41 10.38,71.22 10.38,66.36 10.85,65.89 10.85,61.81 10.68,61.63 10.68,52.02 10.32,51.66 8.2,51.66 7.58,52.29 7.58,70.98 8.01,71.41
HP_OUT_L on BOTTOM: 9.62,4.55 11.08,4.55 11.15,4.48 11.15,3.79 11.08,3.72 9.62,3.72 9.5,3.85 9.5,4.42
HP_OUT_R on BOTTOM: 9.69,2.96 10.96,2.96 11.08,2.83 11.08,2.26 11.02,2.2 9.75,2.2 9.56,2.39 9.56,2.83

Small or netless copper shapes (teardrops, artwork), in the pictures only: 5 on TOP, 4 on BOTTOM

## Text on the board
User.Comments: LSH461P | 2018-11-15 | 2019-11-15 | FPC52 | Steven
Ref Des/Silkscreen Top: 435OV932L01
User.27: GND4
User.28: GND5
User.29: FIGURE | SIZE | 8.0 | 31.0 | 75.0 | 91.0 | 98.0 | 55.0x24.0 | 71.0x31.0 | 94.0x31.0 | DRILL CHART: TOP to BOTTOM | ALL UNITS ARE IN MILS | TOLERANCE | +3.0/-3.0 | PLATED | QTY | 287 | 18 | 2 | 1 | 7 | 4
User.31: test_170814_HR_1_4mm-6L and 8L and 10L(5mil 50 ohm)_170804(FB) | 5 mil | 5/5.1mil | 5.3/5.7mil
